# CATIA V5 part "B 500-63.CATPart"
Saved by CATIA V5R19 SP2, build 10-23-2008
Part number: B 500-63
Bounding box of the stored display mesh (mm): x -18.951 to 18.951, y -18.952 to 18.952, z 0 to 177
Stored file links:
  C:\Users\Bora\Desktop\3D Katı model\B serisi\B 500\B 500-63.CATPart
  C:\Program Files\Dassault Systemes\B19\intel_a\reffiles\standard\MetricThickPitch.txt
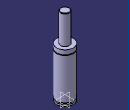
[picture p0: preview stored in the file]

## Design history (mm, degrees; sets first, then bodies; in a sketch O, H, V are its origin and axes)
Body1 (main body)
  Sketch1 on yz-plane, origin (0, 0, 0), H (0, 1, 0), V (0, 0, 1)
    point P3 (10, 176)
    point P5 (10, 176)
    point P7 (19, 102.5)
    point P8 (19, 100.5)
    point P12 (19, 100.5)
    point P13 (19, 102.5)
    line L1 (19, 0) -> (19, 4)
    line L2 (10, 176) -> (10, 112)
    arc A1 centre (9, 176) radius 1 from (10, 176) to (9, 177) ccw
    arc A2 centre (19, 101.5) radius 1 from (19, 102.5) to (19, 100.5) ccw
    line L3 (16.5, 7.5) -> (16.5, 4)
    line L4 (19, 7.5) -> (19, 100.5)
    line L5 (19, 102.5) -> (19, 112)
    line L6 (9, 177) -> (0, 177)
    point P15 (0, 177)
    line L7 (10, 112) -> (19, 112)
    line L8 (0, 0) -> (19, 0)
    line L9 (16.5, 7.5) -> (19, 7.5)
    line L10 (16.5, 4) -> (19, 4)
    coincidence: P15 V, P3 P5, P7 P13, P8 P12
    tangency: L6 A1
    horizontal: L7 H, L8 H, L9 H, L10 H
  Shaft1: profile Sketch1, axis Sketch1.V, angle 360
  Sketch2 on face of Shaft1 from Sketch1.L8, origin (0, 0, 0), H (1, 0, 0), V (0, -1, 0)
    point P1 (0, 0)
  Hole1: placed by Sketch2, at (0, 0, 0) direction (0, 0, 1), diameter 6.647, depth 7, threaded "M8", thread diameter 8, thread depth 7, pitch 1.25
